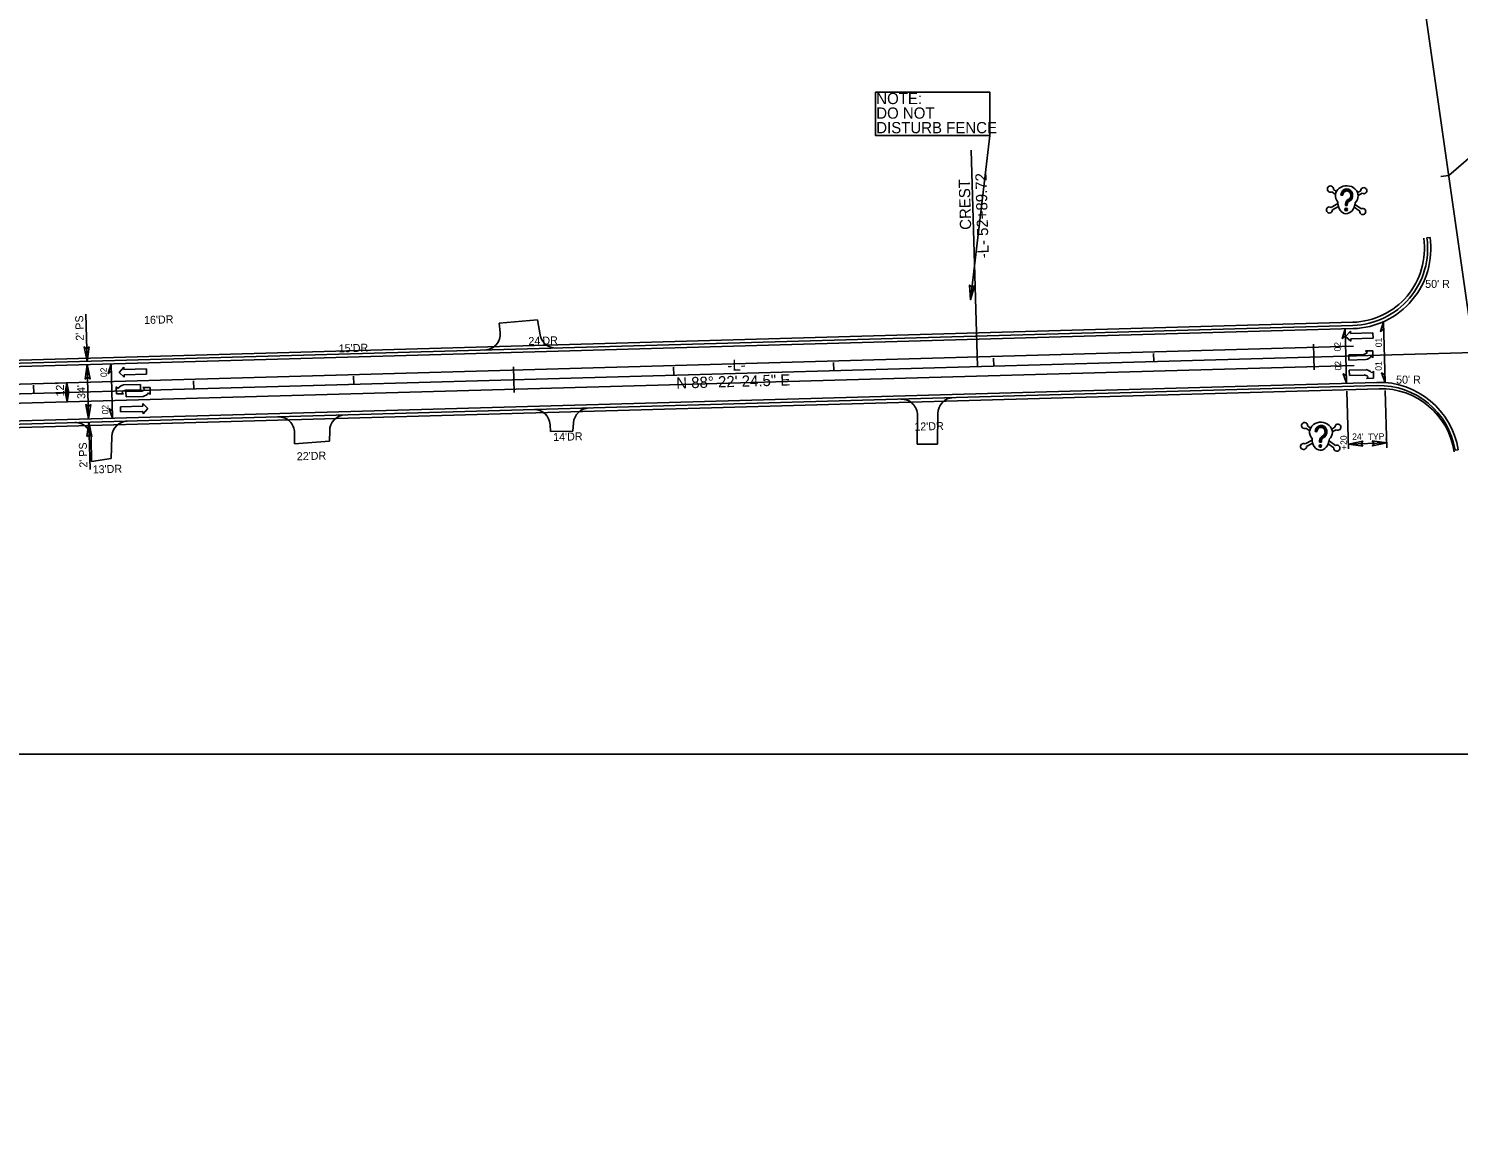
# Model space of a CAD drawing. Extents: x 1755545 to 1761252, y 736169 to 737766.
# Drawn here: x 1759380 to 1760273, y 736573 to 737259 of the extents above; entities that cross this region are included whole.
import ezdxf

# ---------------------------------------------------------------- set-up
doc = ezdxf.new("R2010")
doc.units = 0
for name, color, linetype in [('Default', 7, 'Continuous'), ('Exist Contamination Potential Cell', 7, 'Continuous'), ('Exist Cultural Church Label', 7, 'Continuous'), ('Old_Level_1', 7, 'Continuous'), ('Old_Level_15', 7, 'Continuous'), ('Prop Dimension', 7, 'Continuous'), ('Prop Horizontal Alignment', 7, 'Continuous'), ('Prop Horizontal Alignment Direction Label', 7, 'Continuous'), ('Prop Horizontal Alignment Station Label', 7, 'Continuous'), ('Prop Horizontal Alignment Tick Large', 7, 'Continuous'), ('Prop Horizontal Alignment Tick Small', 7, 'Continuous'), ('Prop Lane Arrow CELL', 7, 'Continuous'), ('Prop Lane Lines', 7, 'Continuous'), ('Prop Paved Shoulder', 7, 'Continuous'), ('Prop Shade Light', 7, 'Continuous'), ('Prop Superelevation Label', 7, 'Continuous'), ('Prop Terminator CELL', 7, 'Continuous'), ('Scratch_Level_4', 7, 'Continuous'), ('Scratch_Level_5', 7, 'Continuous'), ('Scratch_Level_6', 7, 'Continuous')]:
    doc.layers.add(name, color=color, linetype=linetype)

msp = doc.modelspace()

# ---------------------------------------------------------------- linework, layer by layer
at = {"layer": 'Default'}
for p, q in [((1760193.92, 737156.72), (1760196.24, 737155.1)), ((1760194.94, 737158.18), (1760196.81, 737156.87)), ((1760199.63, 737154.6), (1760200.76, 737154.55)), ((1760211.97, 737157.35), (1760209.98, 737156.23)), ((1760212.85, 737155.8), (1760210.38, 737154.41)), ((1760197.75, 737149.35), (1760193.44, 737146.92)), ((1760198.06, 737147.48), (1760194.32, 737145.37)), ((1760202.47, 737149.1), (1760202.42, 737148.11)), ((1760202.42, 737148.11), (1760203.55, 737148.05)), ((1760202.63, 737149.1), (1760202.58, 737148.1)), ((1760202.79, 737149.09), (1760202.74, 737148.09)), ((1760202.95, 737149.08), (1760202.9, 737148.09)), ((1760203.11, 737149.07), (1760203.07, 737148.08)), ((1760203.17, 737151.94), (1760203.17, 737151.94)), ((1760203.28, 737149.06), (1760203.23, 737148.07)), ((1760203.44, 737149.06), (1760203.39, 737148.06)), ((1760203.6, 737149.05), (1760203.55, 737148.05)), ((1760207.83, 737147), (1760211.35, 737144.54)), ((1760208.32, 737148.83), (1760212.37, 737146.01)), ((1760177.78, 737008.99), (1760180.1, 737007.37)), ((1760178.8, 737010.45), (1760180.68, 737009.14)), ((1760183.49, 737006.87), (1760184.62, 737006.82)), ((1760187.04, 737004.21), (1760187.04, 737004.21)), ((1760195.84, 737009.62), (1760193.84, 737008.5)), ((1760196.71, 737008.07), (1760194.25, 737006.68)), ((1760181.61, 737001.61), (1760177.31, 736999.19)), ((1760181.93, 736999.74), (1760178.18, 736997.64)), ((1760186.33, 737001.37), (1760186.29, 737000.38)), ((1760186.29, 737000.38), (1760187.42, 737000.32)), ((1760186.5, 737001.36), (1760186.45, 737000.37)), ((1760186.66, 737001.36), (1760186.61, 737000.36)), ((1760186.82, 737001.35), (1760186.77, 737000.35)), ((1760186.98, 737001.34), (1760186.93, 737000.35)), ((1760187.14, 737001.33), (1760187.09, 737000.34)), ((1760187.3, 737001.32), (1760187.26, 737000.33)), ((1760187.47, 737001.32), (1760187.42, 737000.32)), ((1760191.7, 736999.27), (1760195.22, 736996.81)), ((1760192.19, 737001.1), (1760196.24, 736998.27))]:
    msp.add_line(p, q, dxfattribs=at)
for centre, radius in [((1760202.91, 737145.62), 0.81), ((1760202.91, 737145.62), 0.63), ((1760202.91, 737145.62), 0.446), ((1760202.91, 737145.62), 0.266), ((1760202.91, 737145.62), 0.0863), ((1760186.77, 736997.89), 0.81), ((1760186.77, 736997.89), 0.63), ((1760186.77, 736997.89), 0.446), ((1760186.77, 736997.89), 0.266), ((1760186.77, 736997.89), 0.0863)]:
    msp.add_circle(centre, radius, dxfattribs=at)
for centre, start, end in [((1760193.05, 737158.41), 353.12417, 297.03272), ((1760213.87, 737157.4), 237.42038, 181.32894), ((1760192.42, 737145.33), 57.42038, 1.32894), ((1760213.24, 737144.32), 173.12417, 117.03272), ((1760176.92, 737010.68), 353.12417, 297.03272), ((1760197.74, 737009.67), 237.42038, 181.32894), ((1760176.29, 736997.59), 57.42038, 1.32894), ((1760197.1, 736996.58), 173.12417, 117.03272)]:
    msp.add_arc(centre, 1.9, start, end, dxfattribs=at)
for centre, major_axis, ratio, start_param, end_param in [((1760203.28, 737154.19), (7.1, -0.34), 0.885014, 5.564242, 10.143721), ((1760203.29, 737154.42), (0.2, 4.08), 0.9, 3.567618, 7.853982), ((1760203.29, 737154.42), (0.19, 3.9), 0.9, 3.567618, 7.853982), ((1760203.29, 737154.42), (0.18, 3.72), 0.9, 3.567618, 7.853982), ((1760203.29, 737154.42), (0.17, 3.54), 0.9, 3.567618, 7.853982), ((1760203.29, 737154.42), (0.16, 3.36), 0.9, 3.567618, 7.853982), ((1760203.29, 737154.42), (0.15, 3.18), 0.9, 3.567618, 7.853982), ((1760203.29, 737154.42), (0.15, 3), 0.9, 3.567618, 7.853982), ((1760203.29, 737154.42), (0.14, 2.82), 0.9, 3.567618, 7.853982), ((1760203.08, 737150.12), (-0.34, -7.1), 0.752542, 4.722735, 7.843636), ((1760205.22, 737148.97), (0.15, 3.06), 0.9, 0.426026, 1.570796), ((1760205.22, 737148.97), (0.14, 2.88), 0.9, 0.426026, 1.570796), ((1760205.22, 737148.97), (0.13, 2.7), 0.9, 0.426026, 1.570796), ((1760205.22, 737148.97), (0.12, 2.52), 0.9, 0.426026, 1.570796), ((1760205.22, 737148.97), (0.11, 2.34), 0.9, 0.426026, 1.570796), ((1760205.22, 737148.97), (0.1, 2.16), 0.9, 0.426026, 1.570796), ((1760205.22, 737148.97), (0.1, 1.98), 0.9, 0.426026, 1.570796), ((1760205.22, 737148.97), (0.09, 1.8), 0.9, 0.426026, 1.570796), ((1760187.15, 737006.46), (7.1, -0.34), 0.885014, 5.564242, 10.143721), ((1760186.95, 737002.39), (-0.34, -7.1), 0.752542, 4.722735, 7.843636), ((1760187.16, 737006.69), (0.2, 4.08), 0.9, 3.567618, 7.853982), ((1760187.16, 737006.69), (0.19, 3.9), 0.9, 3.567618, 7.853982), ((1760187.16, 737006.69), (0.18, 3.72), 0.9, 3.567618, 7.853982), ((1760187.16, 737006.69), (0.17, 3.54), 0.9, 3.567618, 7.853982), ((1760187.16, 737006.69), (0.16, 3.36), 0.9, 3.567618, 7.853982), ((1760187.16, 737006.69), (0.15, 3.18), 0.9, 3.567618, 7.853982), ((1760187.16, 737006.69), (0.15, 3), 0.9, 3.567618, 7.853982), ((1760187.16, 737006.69), (0.14, 2.82), 0.9, 3.567618, 7.853982), ((1760189.08, 737001.24), (0.15, 3.06), 0.9, 0.426026, 1.570796), ((1760189.08, 737001.24), (0.14, 2.88), 0.9, 0.426026, 1.570796), ((1760189.08, 737001.24), (0.13, 2.7), 0.9, 0.426026, 1.570796), ((1760189.08, 737001.24), (0.12, 2.52), 0.9, 0.426026, 1.570796), ((1760189.08, 737001.24), (0.11, 2.34), 0.9, 0.426026, 1.570796), ((1760189.08, 737001.24), (0.1, 2.16), 0.9, 0.426026, 1.570796), ((1760189.08, 737001.24), (0.1, 1.98), 0.9, 0.426026, 1.570796), ((1760189.08, 737001.24), (0.09, 1.8), 0.9, 0.426026, 1.570796)]:
    msp.add_ellipse(centre, major_axis=major_axis, ratio=ratio, start_param=start_param, end_param=end_param, dxfattribs=at)
at = {"layer": 'Exist Contamination Potential Cell'}
for p, q in [((1759014.29, 737037.34), (1760207.22, 737071.22)), ((1757498.66, 736960.29), (1760222.11, 737037.63))]:
    msp.add_line(p, q, dxfattribs=at)
for centre, start, end in [((1760205.8, 737121.2), 271.62654, 8.09005), ((1760223.53, 736987.65), 9.08723, 91.62654)]:
    msp.add_arc(centre, 50, start, end, dxfattribs=at)
at = {"layer": 'Exist Cultural Church Label'}
for points in [[(1760226.12, 737075.51), (1760224.29, 737069.46), (1760226.25, 737070.89)], [(1760202.24, 737071.08), (1760200.41, 737065.02), (1760202.37, 737066.45)], [(1759431.31, 737049.19), (1759429.48, 737043.13), (1759431.44, 737044.56)], [(1760203.2, 737037.09), (1760201.03, 737043.03), (1760203.07, 737041.71)], [(1760227.2, 737037.62), (1760225.03, 737043.56), (1760227.06, 737042.25)], [(1759432.27, 737015.2), (1759430.11, 737021.14), (1759432.14, 737019.82)]]:
    msp.add_lwpolyline(points, close=True, dxfattribs=at)
at = {"layer": 'Old_Level_1'}
for p, q in [((1759673.77, 737074.72), (1759697.59, 737076.74)), ((1759673.77, 737074.72), (1759674.33, 737068.73)), ((1759697.59, 737076.74), (1759699.38, 737067.28)), ((1759719.8, 737007.12), (1759720.18, 737012.38)), ((1759935.02, 737017.12), (1759934.9, 736998.96)), ((1759947.77, 737018.18), (1759947.64, 736999.01)), ((1759419.11, 736988.16), (1759418.88, 737002.69)), ((1759431.3, 736990.07), (1759431.72, 737003.76)), ((1759545.86, 736999.22), (1759545.86, 737006.13)), ((1759567.84, 737001), (1759567.85, 737007.34)), ((1759705.77, 737007.02), (1759705.57, 737011.15)), ((1759705.77, 737007.02), (1759719.8, 737007.12)), ((1759545.86, 736999.22), (1759567.84, 737001)), ((1759934.9, 736998.96), (1759947.64, 736999.01)), ((1759419.11, 736988.16), (1759431.3, 736990.07))]:
    msp.add_line(p, q, dxfattribs=at)
for centre, start, end in [((1759664.37, 737067.81), 271.62654, 5.26386), ((1759709.22, 737069.08), 190.39466, 271.62654), ((1759695.59, 737010.67), 2.73954, 91.62654), ((1759730.15, 737011.65), 91.62654, 175.85288), ((1759925.03, 737017.19), 359.62, 91.62654), ((1759957.77, 737018.12), 91.62654, 179.62), ((1759408.88, 737002.53), 0.92895, 91.62654), ((1759441.71, 737003.46), 91.62654, 178.27489), ((1759535.86, 737006.14), 359.95423, 91.62654), ((1759577.85, 737007.33), 91.62654, 179.94551)]:
    msp.add_arc(centre, 10, start, end, dxfattribs=at)
at = {"layer": 'Old_Level_15'}
msp.add_line((1759972.53, 737047.55), (1759968.69, 737182.76), dxfattribs=at)
at = {"layer": 'Prop Dimension'}
for p, q in [((1759980.31, 737191.92), (1759968.19, 737089.24)), ((1759415.42, 737080.23), (1759416.26, 737050.76)), ((1759416.32, 737048.76), (1759417.28, 737014.77)), ((1759403.57, 737037.39), (1759403.91, 737025.4)), ((1759418.17, 736983.31), (1759417.34, 737012.77))]:
    msp.add_line(p, q, dxfattribs=at)
msp.add_lwpolyline([(1759908.83, 737218.86), (1759980.31, 737218.86), (1759980.31, 737191.92), (1759908.83, 737191.92)], close=True, dxfattribs=at)
at = {"layer": 'Prop Horizontal Alignment'}
for p, q in [((1760351.41, 736572.88), (1760210.68, 737562.93)), ((1757285.64, 736971.25), (1760282.69, 737056.35))]:
    msp.add_line(p, q, dxfattribs=at)
at = {"layer": 'Prop Horizontal Alignment Station Label'}
msp.add_line((1760266.97, 737166.91), (1760365.6, 737252.04), dxfattribs=at)
at = {"layer": 'Prop Horizontal Alignment Tick Large'}
for p, q in [((1760182.73, 737053.52), (1760182.5, 737061.51)), ((1759682.93, 737039.32), (1759682.7, 737047.32)), ((1760182.73, 737053.52), (1760182.96, 737045.52)), ((1759682.93, 737039.32), (1759683.16, 737031.33))]:
    msp.add_line(p, q, dxfattribs=at)
at = {"layer": 'Prop Horizontal Alignment Tick Small'}
for p, q in [((1760266.97, 737166.91), (1760262.02, 737166.21)), ((1759882.85, 737045), (1759882.71, 737050)), ((1759982.81, 737047.84), (1759982.67, 737052.84)), ((1760082.77, 737050.68), (1760082.63, 737055.68)), ((1759483.01, 737033.65), (1759482.87, 737038.64)), ((1759582.97, 737036.48), (1759582.83, 737041.48)), ((1759782.89, 737042.16), (1759782.75, 737047.16)), ((1759383.05, 737030.81), (1759382.91, 737035.81))]:
    msp.add_line(p, q, dxfattribs=at)
at = {"layer": 'Prop Lane Arrow CELL'}
for p, q in [((1760202.53, 737066.36), (1760205.59, 737069.65)), ((1760205.77, 737063.35), (1760202.53, 737066.36)), ((1760205.59, 737069.65), (1760205.63, 737068.15)), ((1760205.63, 737068.15), (1760219.62, 737068.55)), ((1760219.72, 737065.25), (1760205.72, 737064.85)), ((1760219.62, 737068.55), (1760219.72, 737065.25)), ((1760205.72, 737064.85), (1760205.77, 737063.35)), ((1760219.56, 737057.44), (1760215.06, 737057.37)), ((1760215.06, 737057.37), (1760216.14, 737056.35)), ((1760219.64, 737053.04), (1760219.56, 737057.44)), ((1760213.68, 737055.13), (1760204.53, 737054.87)), ((1760204.53, 737054.87), (1760204.62, 737051.57)), ((1760204.62, 737051.57), (1760215.17, 737051.87)), ((1760218.56, 737054.06), (1760219.64, 737053.04)), ((1759436.25, 737043.88), (1759439.31, 737047.16)), ((1759439.48, 737040.87), (1759436.25, 737043.88)), ((1759439.31, 737047.16), (1759439.35, 737045.66)), ((1759439.35, 737045.66), (1759453.34, 737046.06)), ((1759453.44, 737042.76), (1759439.44, 737042.37)), ((1759439.44, 737042.37), (1759439.48, 737040.87)), ((1759453.34, 737046.06), (1759453.44, 737042.76)), ((1760204.8, 737045.27), (1760215.35, 737045.56)), ((1760204.9, 737041.97), (1760204.8, 737045.27)), ((1760214.04, 737042.23), (1760204.9, 737041.97)), ((1760215.56, 737040.07), (1760216.58, 737041.15)), ((1760220.05, 737040.25), (1760215.56, 737040.07)), ((1760218.86, 737043.56), (1760219.88, 737044.64)), ((1760219.88, 737044.64), (1760220.05, 737040.25)), ((1759435.65, 737033.83), (1759434.52, 737034.85)), ((1759434.52, 737034.85), (1759434.64, 737030.4)), ((1759434.64, 737030.4), (1759439.14, 737030.53)), ((1759439.14, 737030.53), (1759438.06, 737031.55)), ((1759449.58, 737036.33), (1759439.03, 737036.03)), ((1759440.53, 737032.77), (1759449.67, 737033.03)), ((1759449.75, 737032.13), (1759440.6, 737031.87)), ((1759440.6, 737031.87), (1759440.7, 737028.57)), ((1759449.67, 737033.03), (1759449.58, 737036.33)), ((1759455.64, 737034.45), (1759451.14, 737034.37)), ((1759451.14, 737034.37), (1759452.22, 737033.35)), ((1759454.63, 737031.07), (1759455.71, 737030.05)), ((1759455.71, 737030.05), (1759455.64, 737034.45)), ((1759437.13, 737022.45), (1759451.13, 737022.85)), ((1759437.23, 737019.15), (1759437.13, 737022.45)), ((1759440.7, 737028.57), (1759451.24, 737028.87)), ((1759451.13, 737022.85), (1759451.09, 737024.35)), ((1759451.09, 737024.35), (1759454.32, 737021.34)), ((1759454.32, 737021.34), (1759451.26, 737018.05)), ((1759451.22, 737019.55), (1759437.23, 737019.15)), ((1759451.26, 737018.05), (1759451.22, 737019.55))]:
    msp.add_line(p, q, dxfattribs=at)
for centre, radius, start, end in [((1760213.6, 737058.38), 3.28, 271.62654, 321.28471), ((1760214.23, 737057.02), 5.25, 280.30261, 325.6143), ((1760214.15, 737038.97), 3.28, 41.96836, 91.62654), ((1760214.7, 737040.37), 5.25, 37.63877, 82.95046), ((1759439.96, 737030.85), 5.25, 100.30261, 145.6143), ((1759440.6, 737029.48), 3.28, 91.62654, 141.28471), ((1759449.67, 737035.39), 3.28, 271.62654, 321.28471), ((1759450.3, 737034.02), 5.25, 280.30261, 325.6143)]:
    msp.add_arc(centre, radius, start, end, dxfattribs=at)
at = {"layer": 'Prop Lane Lines'}
for p, q in [((1757285.47, 736977.25), (1760207.53, 737060.22)), ((1757285.81, 736965.25), (1760207.87, 737048.23))]:
    msp.add_line(p, q, dxfattribs=at)
at = {"layer": 'Prop Paved Shoulder'}
for p, q in [((1760253.32, 737127.95), (1760255.3, 737128.23)), ((1759262.66, 737046.4), (1760207.16, 737073.22)), ((1759121.42, 737004.37), (1760222.17, 737035.63)), ((1760270.92, 736995.26), (1760272.9, 736995.54))]:
    msp.add_line(p, q, dxfattribs=at)
for centre, start, end in [((1760205.8, 737121.2), 271.62654, 8.09005), ((1760223.53, 736987.65), 9.12879, 91.62654)]:
    msp.add_arc(centre, 48, start, end, dxfattribs=at)
at = {"layer": 'Prop Shade Light'}
for p, q in [((1760255.3, 737128.23), (1760253.32, 737127.95)), ((1759014.29, 737037.34), (1760207.22, 737071.22)), ((1760207.16, 737073.22), (1759254.68, 737046.17)), ((1760222.11, 737037.63), (1757498.66, 736960.29)), ((1759121.42, 737004.37), (1760222.17, 737035.63)), ((1760270.92, 736995.26), (1760272.9, 736995.54))]:
    msp.add_line(p, q, dxfattribs=at)
for centre, radius, start, end in [((1760205.8, 737121.2), 48, 271.62654, 8.09005), ((1760205.8, 737121.2), 50, 271.62654, 8.09005), ((1760223.53, 736987.65), 50, 9.08723, 91.62654), ((1760223.53, 736987.65), 48, 9.12879, 91.62654)]:
    msp.add_arc(centre, radius, start, end, dxfattribs=at)
at = {"layer": 'Prop Superelevation Label'}
for p, q in [((1760227.2, 737037.62), (1760226.12, 737075.51)), ((1760203.2, 737037.09), (1760202.24, 737071.08)), ((1759431.31, 737049.19), (1759432.27, 737015.2)), ((1760204.37, 736996.11), (1760203.34, 737032.09)), ((1760228.36, 736996.79), (1760227.34, 737032.62)), ((1760204.28, 736999.11), (1760228.27, 736999.79))]:
    msp.add_line(p, q, dxfattribs=at)
at = {"layer": 'Prop Terminator CELL'}
for points in [[(1759970.79, 737098), (1759968.19, 737089.24), (1759967.66, 737098.42), (1759969.12, 737097.09)], [(1759417.55, 737059.8), (1759416.26, 737050.76), (1759414.4, 737059.76), (1759416.03, 737058.66)], [(1759415.02, 737039.72), (1759416.32, 737048.76), (1759418.17, 737039.76), (1759416.54, 737040.86)], [(1759404.82, 737031.73), (1759403.91, 737025.4), (1759402.61, 737031.7), (1759403.75, 737030.93)], [(1759402.66, 737031.06), (1759403.57, 737037.39), (1759404.87, 737031.09), (1759403.73, 737031.87)], [(1759418.57, 737023.81), (1759417.28, 737014.77), (1759415.42, 737023.77), (1759417.06, 737022.67)], [(1759416.04, 737003.73), (1759417.34, 737012.77), (1759419.19, 737003.77), (1759417.56, 737004.88)], [(1760213.32, 736997.81), (1760204.28, 736999.11), (1760213.28, 737000.96), (1760212.18, 736999.33)], [(1760219.23, 737001.08), (1760228.27, 736999.79), (1760219.27, 736997.93), (1760220.37, 736999.56)]]:
    msp.add_lwpolyline(points, close=True, dxfattribs=at)
at = {"layer": 'Scratch_Level_5'}
msp.add_lwpolyline([(1759122.38, 737765.89), (1760563.07, 737765.89), (1760563.07, 736805.42), (1759122.38, 736805.42)], close=True, dxfattribs=at)
at = {"layer": 'Scratch_Level_6'}
for p, q in [((1759262.62, 737048.4), (1760207.1, 737075.22)), ((1759129.47, 737002.6), (1760223.47, 737033.66))]:
    msp.add_line(p, q, dxfattribs=at)
for centre, start, end in [((1760205.8, 737121.2), 271.62654, 8.09005), ((1760224.77, 736987.68), 8.09005, 91.62654)]:
    msp.add_arc(centre, 46, start, end, dxfattribs=at)

# ---------------------------------------------------------------- texts
at = {"layer": 'Old_Level_15'}
for s, p in [('CREST', (1759968.66, 737133.03)), ('-L- 52+89.72', (1759979.67, 737115.18))]:
    msp.add_text(s, height=7, rotation=91.62654, dxfattribs=at).set_placement(p)
at = {"layer": 'Prop Dimension'}
for s, height, p in [('NOTE:', 7, (1759909.32, 737211.46)), ('DO NOT ', 7, (1759909.32, 737202.36)), ('DISTURB FENCE', 7, (1759909.32, 737193.26)), ("50' R", 5, (1760252.26, 737096.66)), ("50' R", 5, (1760234.09, 737036.86))]:
    msp.add_text(s, height=height, dxfattribs=at).set_placement(p)
for s, p in [("2' PS", (1759414.28, 737063.76)), ("12'", (1759401.97, 737028.87)), ("34'", (1759415.2, 737027.35)), ("2' PS", (1759416.53, 736984.43))]:
    msp.add_text(s, height=5, rotation=91.62654, dxfattribs=at).set_placement(p)
at = {"layer": 'Prop Horizontal Alignment Direction Label'}
for s, p in [('-L-', (1759816.46, 737044.78)), ('N 88%%d 22\' 24.5" E', (1759784.45, 737033.72))]:
    msp.add_text(s, height=7, rotation=1.62654, dxfattribs=at).set_placement(p)
at = {"layer": 'Prop Superelevation Label'}
for s, rotation, p in [('01', 91.62654, (1760225.27, 737059.63)), ('02', 91.62654, (1760199.56, 737056.97)), ('02', 91.62654, (1760199.89, 737045.11)), ('01', 91.62654, (1760225.17, 737044.96)), ('02', 91.62654, (1759428.73, 737041.01)), ('02', 91.62654, (1759429.64, 737017.72)), ('+20', 91.62654, (1760203.48, 736995.5)), ("24'", 1.62654, (1760206.68, 737001.69)), ('TYP.', 1.62654, (1760216.43, 737001.64))]:
    msp.add_text(s, height=4, rotation=rotation, dxfattribs=at).set_placement(p)
at = {"layer": 'Scratch_Level_4'}
for s, p in [("16'DR", (1759451.94, 737074.08)), ("24'DR", (1759692.08, 737060.93)), ("15'DR", (1759573.59, 737056.31)), ("12'DR", (1759933.18, 737007.45)), ("14'DR", (1759707.55, 737001)), ("22'DR", (1759547.36, 736988.95)), ("13'DR", (1759419.87, 736980.73))]:
    msp.add_text(s, height=5, rotation=1.62654, dxfattribs=at).set_placement(p)

doc.saveas('drawing.dxf')
